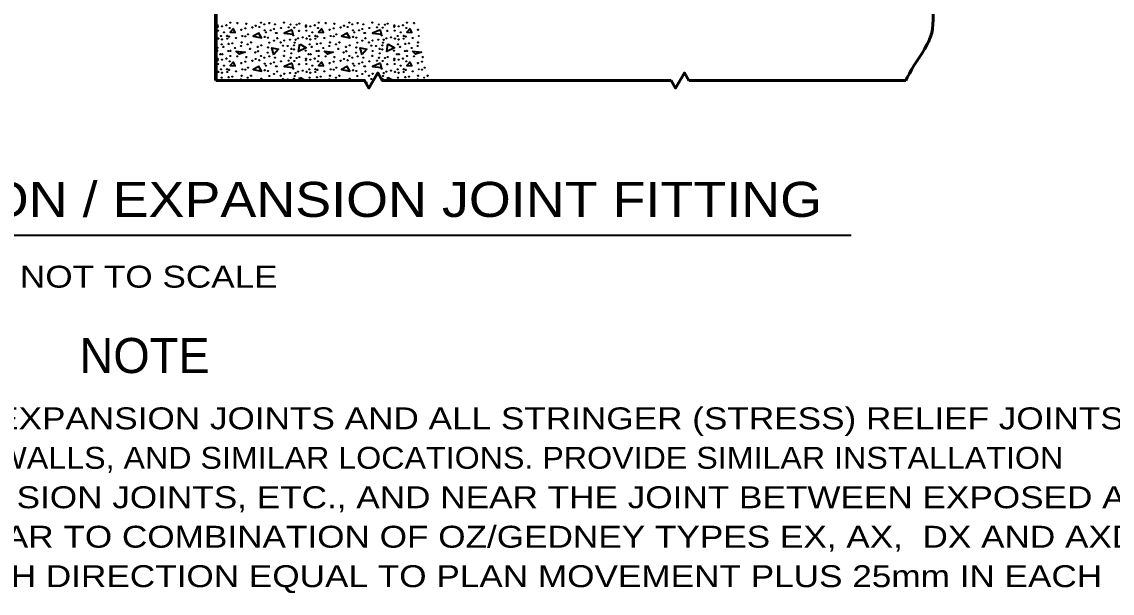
# Model space of a CAD drawing. Extents: x -50 to 806, y -9 to 535.
# Drawn here: x 241 to 390.3, y 283.1 to 361.3 of the extents above; entities that cross this region are included whole.
import ezdxf

# ---------------------------------------------------------------- set-up
doc = ezdxf.new("R2010")
doc.units = 0
doc.header["$LTSCALE"] = 1.2
doc.layers.add('1', color=7, linetype='Continuous', lineweight=35)

msp = doc.modelspace()

# ---------------------------------------------------------------- linework, layer by layer
at = {"layer": '1', "lineweight": 70}
msp.add_line((267.521, 353.251), (267.521, 372.467), dxfattribs=at)
at = {"layer": '1'}
for p, q in [((267.521, 353.348), (267.691, 353.251)), ((278.962, 353.251), (279.024, 353.684)), ((279.072, 353.66), (279.787, 353.251)), ((291.058, 353.251), (291.12, 353.684)), ((291.168, 353.66), (291.883, 353.251))]:
    msp.add_line(p, q, dxfattribs=at)
at = {"layer": '1', "lineweight": 53}
for p, q in [((296.916, 353.251), (329.921, 353.251)), ((332.321, 353.251), (362.087, 353.251))]:
    msp.add_line(p, q, dxfattribs=at)
at = {"layer": '1', "lineweight": 40}
msp.add_line((163.144, 332.08), (354.554, 332.08), dxfattribs=at)
at = {"layer": '1'}
for points in [[(269.952, 360.356), (269.496, 359.876), (270.192, 359.828), (269.952, 360.308)], [(278.016, 360.188), (276.888, 359.732), (278.136, 359.588), (278.016, 360.14)], [(282.048, 360.356), (281.592, 359.876), (282.288, 359.828), (282.048, 360.308)], [(290.112, 360.188), (288.984, 359.732), (290.232, 359.588), (290.112, 360.14)], [(294.144, 360.356), (293.688, 359.876), (294.384, 359.828), (294.144, 360.308)], [(273.432, 359.732), (272.64, 359.3), (273.816, 359.084), (273.384, 359.756)], [(285.528, 359.732), (284.736, 359.3), (285.912, 359.084), (285.48, 359.756)], [(267.521, 357.908), (267.816, 357.74), (267.521, 357.596)], [(275.496, 356.78), (275.208, 357.74), (276.144, 357.548), (275.472, 356.828)], [(279.072, 358.22), (279.912, 357.74), (278.88, 357.236), (279.024, 358.244)], [(287.592, 356.78), (287.304, 357.74), (288.24, 357.548), (287.568, 356.828)], [(291.168, 358.22), (292.008, 357.74), (290.976, 357.236), (291.12, 358.244)], [(269.952, 355.796), (269.496, 355.316), (270.192, 355.268), (269.952, 355.748)], [(278.016, 355.628), (276.888, 355.172), (278.136, 355.028), (278.016, 355.58)], [(282.048, 355.796), (281.592, 355.316), (282.288, 355.268), (282.048, 355.748)], [(290.112, 355.628), (288.984, 355.172), (290.232, 355.028), (290.112, 355.58)], [(294.144, 355.796), (293.688, 355.316), (294.384, 355.268), (294.144, 355.748)], [(273.432, 355.172), (272.64, 354.74), (273.816, 354.524), (273.384, 355.196)], [(285.528, 355.172), (284.736, 354.74), (285.912, 354.524), (285.48, 355.196)], [(288.051, 353.026), (288.24, 352.988), (288.137, 352.877)]]:
    msp.add_lwpolyline(points, dxfattribs=at)
for points in [[(270.288, 357.284), (271.536, 357.14), (270.72, 356.852)], [(282.384, 357.284), (283.632, 357.14), (282.816, 356.852)], [(294.48, 357.284), (295.728, 357.14), (294.912, 356.852)]]:
    msp.add_lwpolyline(points, close=True, dxfattribs=at)
at = {"layer": '1', "lineweight": 53}
for points in [[(297.026, 353.251), (290.321, 353.251), (289.721, 354.29), (288.521, 352.212), (287.921, 353.251), (267.521, 353.251)], [(329.921, 353.251), (330.521, 352.212), (331.721, 354.29), (332.321, 353.251)]]:
    msp.add_lwpolyline(points, dxfattribs=at)
at = {"layer": '1'}
for centre in [(267.791, 360.599), (267.807, 360.8), (267.839, 360.058), (268.395, 360.663), (268.984, 360.816), (269.422, 360.44), (269.534, 361.15), (270.504, 361.103), (271.029, 360.186), (271.569, 360.392), (271.697, 361.007), (272.54, 360.504), (273.017, 360.737), (273.494, 360.583), (273.732, 361.166), (274.162, 360.927), (274.241, 360.106), (274.861, 361.103), (275.052, 360.106), (275.529, 360.297), (275.641, 360.927), (276.468, 360.424), (276.865, 361.182), (277.533, 360.536), (277.788, 360.912), (278.297, 360.488), (278.631, 360.88), (278.933, 360.042), (278.965, 361.023), (279.887, 360.599), (279.903, 360.8), (279.935, 360.058), (280.491, 360.663), (281.08, 360.816), (281.518, 360.44), (281.63, 361.15), (282.6, 361.103), (283.125, 360.186), (283.665, 360.392), (283.793, 361.007), (284.636, 360.504), (285.113, 360.737), (285.59, 360.583), (285.828, 361.166), (286.258, 360.927), (286.337, 360.106), (286.957, 361.103), (287.148, 360.106), (287.625, 360.297), (287.737, 360.927), (288.564, 360.424), (288.961, 361.182), (289.629, 360.536), (289.884, 360.912), (290.393, 360.488), (290.727, 360.88), (291.029, 360.042), (291.061, 361.023), (291.983, 360.599), (291.999, 360.8), (292.031, 360.058), (292.587, 360.663), (293.176, 360.816), (293.614, 360.44), (293.726, 361.15), (294.696, 361.103), (295.221, 360.186), (267.871, 358.992), (268.252, 359.342), (268.38, 358.865), (268.65, 359.836), (269.079, 359.358), (269.095, 358.977), (269.359, 359.263), (270.297, 359.056), (271.156, 359.327), (271.569, 359.279), (271.951, 359.565), (274.241, 359.215), (274.432, 359.851), (274.702, 359.104), (275.498, 358.706), (275.8, 359.74), (275.863, 359.74), (275.943, 359.04), (276.913, 358.722), (277.692, 358.833), (278.169, 359.422), (278.456, 358.817), (278.79, 359.024), (279.426, 359.167), (279.967, 358.992), (280.348, 359.342), (280.476, 358.865), (280.746, 359.836), (281.175, 359.358), (281.191, 358.977), (281.455, 359.263), (282.393, 359.056), (283.252, 359.327), (283.665, 359.279), (284.047, 359.565), (286.337, 359.215), (286.528, 359.851), (286.798, 359.104), (287.594, 358.706), (287.896, 359.74), (287.959, 359.74), (288.039, 359.04), (289.009, 358.722), (289.788, 358.833), (290.265, 359.422), (290.552, 358.817), (290.886, 359.024), (291.522, 359.167), (292.063, 358.992), (292.444, 359.342), (292.572, 358.865), (292.842, 359.836), (293.271, 359.358), (293.287, 358.977), (293.551, 359.263), (294.489, 359.056), (295.348, 359.327), (267.759, 357.322), (268.316, 358.197), (268.586, 357.847), (269.262, 357.288), (269.286, 358.261), (269.534, 357.306), (269.788, 358.324), (270.186, 357.704), (270.997, 357.974), (271.06, 358.452), (271.887, 358.197), (272.221, 357.577), (272.365, 358.452), (272.937, 357.083), (273.271, 357.847), (273.319, 357.258), (273.764, 358.054), (274.639, 357.052), (274.687, 357.767), (274.846, 358.42), (276.42, 358.452), (276.754, 358.006), (276.945, 357.274), (277.374, 357.974), (277.883, 357.577), (278.233, 357.497), (278.249, 358.07), (278.329, 358.436), (279.855, 357.322), (280.412, 358.197), (280.682, 357.847), (281.358, 357.288), (281.382, 358.261), (281.63, 357.306), (281.884, 358.324), (282.282, 357.704), (283.093, 357.974), (283.156, 358.452), (283.983, 358.197), (284.317, 357.577), (284.461, 358.452), (285.033, 357.083), (285.367, 357.847), (285.415, 357.258), (285.86, 358.054), (286.735, 357.052), (286.783, 357.767), (286.942, 358.42), (288.516, 358.452), (288.85, 358.006), (289.041, 357.274), (289.47, 357.974), (289.979, 357.577), (290.329, 357.497), (290.345, 358.07), (290.425, 358.436), (291.951, 357.322), (292.508, 358.197), (292.778, 357.847), (293.454, 357.288), (293.478, 358.261), (293.726, 357.306), (293.98, 358.324), (294.378, 357.704), (295.189, 357.974), (295.252, 358.452), (267.791, 356.039), (267.807, 356.24), (267.839, 355.498), (268.157, 356.845), (268.395, 356.103), (268.427, 356.845), (268.984, 356.256), (269.422, 355.88), (269.534, 356.59), (270.504, 356.543), (271.029, 355.626), (271.569, 355.832), (271.697, 356.447), (272.54, 355.944), (273.017, 356.177), (273.494, 356.023), (273.732, 356.606), (274.162, 356.367), (274.241, 355.546), (274.861, 356.543), (275.052, 355.546), (275.529, 355.737), (275.641, 356.367), (276.468, 355.864), (276.865, 356.622), (277.533, 355.976), (277.788, 356.352), (277.899, 356.956), (278.297, 355.928), (278.631, 356.32), (278.965, 356.463), (279.887, 356.039), (279.903, 356.24), (279.935, 355.498), (280.253, 356.845), (280.491, 356.103), (280.523, 356.845), (281.08, 356.256), (281.518, 355.88), (281.63, 356.59), (282.6, 356.543), (283.125, 355.626), (283.665, 355.832), (283.793, 356.447), (284.636, 355.944), (285.113, 356.177), (285.59, 356.023), (285.828, 356.606), (286.258, 356.367), (286.337, 355.546), (286.957, 356.543), (287.148, 355.546), (287.625, 355.737), (287.737, 356.367), (288.564, 355.864), (288.961, 356.622), (289.629, 355.976), (289.884, 356.352), (289.995, 356.956), (290.393, 355.928), (290.727, 356.32), (291.061, 356.463), (291.983, 356.039), (291.999, 356.24), (292.031, 355.498), (292.349, 356.845), (292.587, 356.103), (292.619, 356.845), (293.176, 356.256), (293.614, 355.88), (293.726, 356.59), (294.696, 356.543), (295.221, 355.626), (295.761, 355.832), (295.889, 356.447), (267.871, 354.432), (268.252, 354.782), (268.38, 354.305), (268.65, 355.276), (269.079, 354.798), (269.095, 354.417), (269.359, 354.703), (270.297, 354.496), (271.156, 354.767), (271.569, 354.719), (271.951, 355.005), (274.241, 354.655), (274.432, 355.291), (274.702, 354.544), (275.498, 354.146), (275.8, 355.18), (275.863, 355.18), (275.943, 354.48), (276.913, 354.162), (277.692, 354.273), (278.169, 354.862), (278.456, 354.257), (278.79, 354.464), (278.933, 355.482), (279.426, 354.607), (279.967, 354.432), (280.348, 354.782), (280.476, 354.305), (280.746, 355.276), (281.175, 354.798), (281.191, 354.417), (281.455, 354.703), (282.393, 354.496), (283.252, 354.767), (283.665, 354.719), (284.047, 355.005), (286.337, 354.655), (286.528, 355.291), (286.798, 354.544), (287.594, 354.146), (287.896, 355.18), (287.959, 355.18), (288.039, 354.48), (289.009, 354.162), (289.788, 354.273), (290.265, 354.862), (290.552, 354.257), (290.886, 354.464), (291.029, 355.482), (291.522, 354.607), (292.063, 354.432), (292.444, 354.782), (292.572, 354.305), (292.842, 355.276), (293.271, 354.798), (293.287, 354.417), (293.551, 354.703), (294.489, 354.496), (295.348, 354.767), (295.761, 354.719), (296.143, 355.005), (268.316, 353.637), (268.586, 353.287), (269.286, 353.701), (269.788, 353.764), (270.997, 353.414), (271.06, 353.892), (271.887, 353.637), (272.365, 353.892), (273.271, 353.287), (273.764, 353.494), (274.846, 353.86), (276.42, 353.892), (276.754, 353.446), (277.374, 353.414), (278.249, 353.51), (278.329, 353.876), (280.412, 353.637), (280.682, 353.287), (281.382, 353.701), (281.884, 353.764), (283.093, 353.414), (283.156, 353.892), (283.983, 353.637), (284.461, 353.892), (285.367, 353.287), (285.86, 353.494), (286.942, 353.86), (288.516, 353.892), (288.85, 353.446), (290.345, 353.51), (290.425, 353.876), (292.508, 353.637), (292.778, 353.287), (293.478, 353.701), (293.98, 353.764), (295.189, 353.414), (295.252, 353.892), (296.079, 353.637), (296.557, 353.892)]:
    msp.add_circle(centre, 0.0318, dxfattribs=at)
at = {"layer": '1', "lineweight": 53}
msp.add_spline([(368.553, 382.651), (369.313, 378.447), (366.863, 373.666), (366.326, 368.825), (365.728, 364.642), (365.609, 359.741), (364.952, 358.127), (362.263, 353.645), (362.083, 353.242)], degree=3, dxfattribs=at)

# ---------------------------------------------------------------- texts
at = {"layer": '1'}
for s, height, width, p in [('CONDUIT DEFLECTION / EXPANSION JOINT FITTING', 4.8, 1.15, (164.809, 334.577)), ('NOT TO SCALE', 3, 1.2, (240.699, 324.902)), ('PROVIDE DEFLECTION / EXPANSION FITTING AT ALL EXPANSION JOINTS AND ALL STRINGER (STRESS) RELIEF JOINTS IN', 3, 1.2, (112.919, 305.515)), ('BRIDGE STRUCTURES, MEDIANS, PARAPETS, RETAINING WALLS, AND SIMILAR LOCATIONS. PROVIDE SIMILAR INSTALLATION', 3, 1.1, (112.919, 300.115)), ('IN EXPOSED CONDUIT RUNS AS REQUIRED AT EXPANSION JOINTS, ETC., AND NEAR THE JOINT BETWEEN EXPOSED AND', 3, 1.2, (112.919, 294.715)), ('BURIED OR ENCASED CONDUIT. FITTING TO BE SIMILAR TO COMBINATION OF OZ/GEDNEY TYPES EX, AX,  DX AND AXDX', 3, 1.2, (112.919, 289.315)), ('FITTINGS AND SHALL BE SET FOR MOVEMENT IN EACH DIRECTION EQUAL TO PLAN MOVEMENT PLUS 25mm IN EACH', 3, 1.2, (112.919, 283.915))]:
    msp.add_text(s, height=height, dxfattribs=dict(at, width=width)).set_placement(p)
msp.add_text('NOTE', height=4.8, dxfattribs=at).set_placement((248.856, 313.212))

doc.saveas('drawing.dxf')
